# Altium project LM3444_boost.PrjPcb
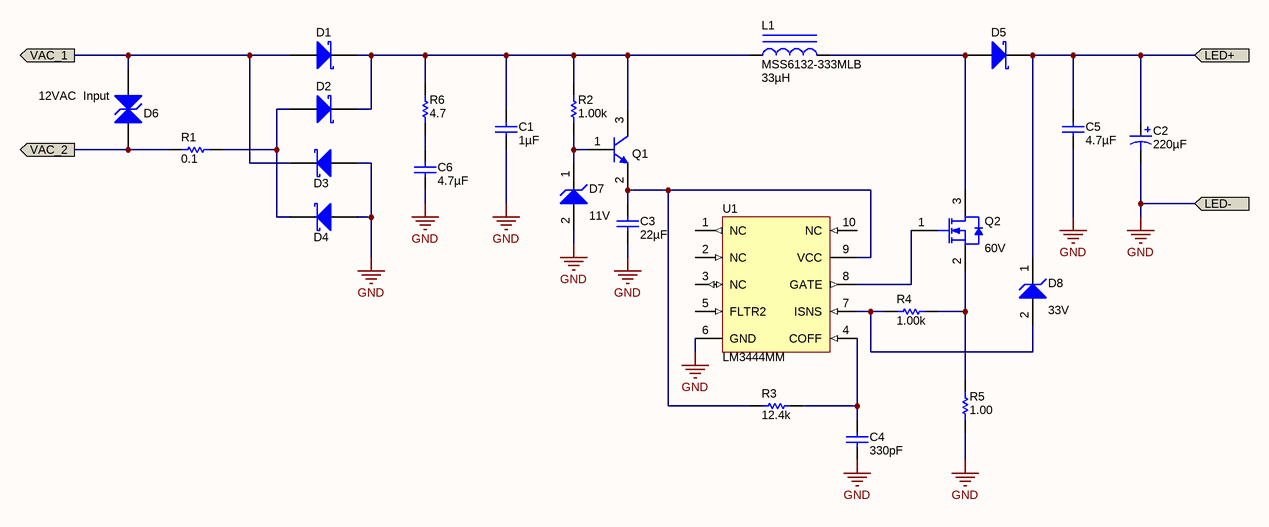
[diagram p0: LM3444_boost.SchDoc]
CopyrightYear: 2011; PCB_CopperRev: 001; PCB_SilkRev: REV A; PRJ_BasePN: xxxxxx; PRJ_Customer: Public Release; PRJ_Title: MR16 Boost Converter; SCH_Rev: 0; TechSupport: http://www.national.com/support
1 sheet, 24 parts. Net scope: flat (ports and power ports of the same name join across sheets).
Board file: MR16_boost.PcbDoc

## Sheet LM3444_boost.SchDoc
size B; Date: Not shown in title block; ApprovedBy: Not shown in title block; CheckedBy: Not shown in title block; Author: Not shown in title block; CompanyName: Not shown in title block; DrawnBy: Not shown in title block; Engineer: Not shown in title block; Organization: Not shown in title block; Address1: Not shown in title block; Address2: Not shown in title block; Address3: Not shown in title block; Address4: Not shown in title block; DocumentNumber: 1; Revision: Use project parameter SCH_Rev; SheetNumber: 1; SheetTotal: 1; PageSetup: Record=PageOptions|CenterHorizontal=True|CenterVertical=True|PrintScale=0.70|XCorrection=1.00|YCorrection=1.00|PrintKind=0|BorderSize=5000000|LeftOffset=0|BottomOffset=0|Orientation=2|PaperLength=1000|PaperWidth=1000|Scale=100|PaperSource=15|PrintQuality=600|MediaType=1|DitherType=10|PaperKind=Letter|PrintScaleMode=1

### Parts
C1  ValueDisplayed: 1µF  [0805_HV]  (hidden comment: GRM216R61E105KA12D)
C2  value 220µF  [Panasonic_ECA_8x11.5mm]  (hidden comment: ECA-1VHG221)
C3  ValueDisplayed: 22µF  [1210]  (hidden comment: GRM32ER61E226KE15L)
C4  ValueDisplayed: 330pF  [0603]  (hidden comment: 06031C331JAT2A)
C5  ValueDisplayed: 4.7µF  [1210]  (hidden comment: GRM32ER71H475KA88L)
C6  ValueDisplayed: 4.7µF  [0805_HV]  (hidden comment: GRM21BR61E475KA12L)
D1  B330A-13-F  [SMA]  (value not drawn)
D2  B330A-13-F  [SMA]  (value not drawn)
D3  B330A-13-F  [SMA]  (value not drawn)
D4  B330A-13-F  [SMA]  (value not drawn)
D5  B330A-13-F  [SMA]  (value not drawn)
D6  SMAJ24CA-13-F  [SMA]  (value not drawn)
D7  value 11V  [SOD-123]  (hidden comment: CMHZ4698)
D8  value 33V  [SOD-123]  (hidden comment: CMHZ4714)
L1  MSS6132-333MLB  ValueDisplayed: 33µH  [MSS6132]
Q1  BC848CLT1G  [SOT-23]  (value not drawn)
Q2  value 60V  [SOT-23]  (hidden comment: 2N7002ET1G)
R1  value 0.1  [0805_HV]  (hidden comment: ERJ-6RSJR10V)
R2  value 1.00k  [0603]  (hidden comment: CRCW06031K00FKEA)
R3  value 12.4k  [0603]  (hidden comment: CRCW060312K4FKEA)
R4  value 1.00k  [0603]  (hidden comment: CRCW06031K00FKEA)
R5  value 1.00  [1206]  (hidden comment: CSR 1/2 1 1 I)
R6  value 4.7  [0805_HV]  (hidden comment: RC0805JR-074R7L)
U1  LM3444MM  [MUB10A_N]

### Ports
LED+, LED-, VAC_1, VAC_2

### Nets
GND: C1.2 C2.2(-) C3.2 C4.2 C5.2 C6.2 D3.1(A) D4.1(A) D7.2(A) R5.1 U1.6(GND) ; port LED-
NetC1_1: C1.1 D1.2(K) D2.2(K) L1.1 Q1.3(C) R2.2 R6.2
NetC2_1: C2.1(+) C5.1 D5.2(K) D8.1(K) ; port LED+
NetC3_1: C3.1 Q1.2(E) R3.1 U1.9(VCC)
NetC4_1: C4.1 R3.2 U1.4(COFF)
NetC6_1: C6.1 R6.1
NetD1_1: D1.1(A) D3.2(K) D6.1(A) ; port VAC_1
NetD2_1: D2.1(A) D4.2(K) R1.2
NetD5_1: D5.1(A) L1.2 Q2.3(D)
NetD6_2: D6.2(K) R1.1 ; port VAC_2
NetD7_1: D7.1(K) Q1.1(B) R2.1
NetD8_2: D8.2(A) R4.2 U1.7(ISNS)
NetQ2_1: Q2.1(G) U1.8(GATE)
NetQ2_2: Q2.2(S) R4.1 R5.2

Not connected (* = marked no-connect by the designer): U1 1(NC) 2(NC) 3(NC) 5(FLTR2) 10(NC)

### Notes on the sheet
- (near D6) 12VAC  Input

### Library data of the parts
C1 = GRM216R61E105KA12D: CAP, CERM, 1uF, 25V, +/-10%, X5R, 0805; Manufacturer: MuRata; Cap_Case: 0805; ESR_Ohm: 0.009; Polarized: N; TaMax_C: 85; TaMin_C: -55; Tolerance_%: 10; VDC_V: 25; Cap_F: 0.000001; CompType: Capacitor; U/M: EA; Value1: 0.009 ohm
C2 = Capacitor_Polarized: CAP, AL, 220µF, 35V, +/-20%, TH bent; Manufacturer: Panasonic - ECG; Polarized: Y; Tolerance_%: 20; U/M: EA; Description: CAP ALUM 220UF 35V 20% RADIAL; Ripple Current: 270mA; Lifetime @ Temp.: 1000 Hrs @ 105°C
C3 = GRM32ER61E226KE15L: CAP, CERM, 22uF, 25V, +/-10%, X5R, 1210; Manufacturer: MuRata; ESR_Ohm: 0.002; Polarized: N; TaMax_C: 85; TaMin_C: -55; Tolerance_%: 10; VDC_V: 25; Cap_F: 0.000022; CompType: Capacitor; U/M: EA; Value1: 0.002 ohm
C4 = 06031C331JAT2A: CAP, CERM, 330pF, 100V, +/-5%, X7R, 0603; Manufacturer: AVX; ESR_Ohm: 0.472; Polarized: N; TaMax_C: 125; TaMin_C: -55; Tolerance_%: 5; VDC_V: 100; Cap_F: 0.00000000033; CompType: Capacitor; U/M: EA; Value1: 0.472 ohm
C5 = GRM32ER71H475KA88L: CAP, CERM, 4.7uF, 50V, +/-10%, X7R, 1210; Manufacturer: MuRata; ESR_Ohm: 0.002; Polarized: N; TaMax_C: 125; TaMin_C: -55; Tolerance_%: 10; VDC_V: 50; Cap_F: 0.0000047; CompType: Capacitor; U/M: EA; Value1: 0.002 ohm
C6 = GRM21BR61E475KA12L: CAP, CERM, 4.7uF, 25V, +/-10%, X5R, 0805; Manufacturer: MuRata; Cap_Case: 0805; ESR_Ohm: 0.004; Polarized: N; TaMax_C: 85; TaMin_C: -55; Tolerance_%: 10; VDC_V: 25; Cap_F: 0.0000047; CompType: Capacitor; U/M: EA; Value1: 0.004 ohm
D1-D5 = B330A-13-F: Diode, Schottky, 30V, 3A, SMA; Manufacturer: Diodes Inc.; RJC_CperW: 25; Vf_V: 0.5; Io_A: 3; Vr_V: 30; TJMax_C: 125; Value: 0.5V
D6 = TVS_Diode: TVS Diode, 400W, 24V, xx%, SMA; Manufacturer: Diodes Inc; CompType: Transorb; U/M: EA; Polarization: Bidirectional; Voltage - Breakdown: 26.7V; Description: TVS BI-DIR 24V 400W SMA
D7 = CMHZ4698: Diode, Zener, 11V, 500mW, SOD-123; Manufacturer: Central Semiconductor; U/M: EA; Power_W: 0.5; Vz: 11; Value1: 0.5W; RJA_CperW: 350
D8 = CMHZ4714: Diode, Zener, 33V, 500mW, SOD-123; Manufacturer: Central Semiconductor; U/M: EA; Power_W: 0.5; Vz: 33; Value1: 0.5W; RJA_CperW: 350
L1 = MSS6132-333MLB: Inductor, Shielded Drum Core, Ferrite, 33uH, 1.1A, 0.31 ohm, SMD; Manufacturer: Coilcraft; Ind_H: 33.0E-6; Imax_A: 1.1; Irms: 1.6A @ 40C rise; Isat: 1.1A @ 30% inductance drop; DCR_ohm: 0.31; U/M: EA
Q1 = BC848CLT1G, ON Semiconductor: Transistor, NPN, 30V, 0.1A, SOT-23; CompType: BJT; U/M: EA; PNP: 0; NPN: 1; Vceo_V: 30; Vcesat1_V: 0.7; Value: 0.7V; IcRated_A: 0.1; HfeMax: 800
Q2 = 2N7002ET1G: MOSFET, N-CH, 60V, 0.26A, SOT-23; Manufacturer: ON Semiconductor; U/M: EA; ChType: N; VdsMax_V: 60; Value1: 3 ohm; Rdson45_Ohm: 3; Value2: 0.81 nC; QgTyp_nC: 0.81; Vgs_V: 20; IdsMax_A: 0.26
R1 = ERJ-6RSJR10V: RES, 0.1 ohm, 5%, 0.125W, 0805; Manufacturer: Panasonic; CompType: Resistor; Tolerance_%: 5; Power_W: 0.125; Value_Code: R100; EIA_Code: E24; U/M: EA
R2 R4 = CRCW06031K00FKEA: RES, 1.00k ohm, 1%, 0.1W, 0603; Manufacturer: Vishay-Dale; CompType: Resistor; Tolerance_%: 1; VDC_V: 75; Power_W: 0.1; Res_ohm: 1000; Value_Code: 1k00; EIA_Code: E96; U/M: EA
R3 = CRCW060312K4FKEA: RES, 12.4k ohm, 1%, 0.1W, 0603; Manufacturer: Vishay-Dale; CompType: Resistor; Tolerance_%: 1; VDC_V: 75; Power_W: 0.1; Res_ohm: 12400; Value_Code: 12k4; EIA_Code: E96; U/M: EA
R5 = CSR 1/2 1 1 I: RES, 1.00 ohm, 1%, 0.5W, 1206; Manufacturer: Stackpole Electronics Inc; CompType: Resistor; Tolerance_%: 1; Power_W: 0.5; Value_Code: 1R00; EIA_Code: E96; U/M: EA
R6 = RC0805JR-074R7L: RES, 4.7 ohm, 5%, 0.125W, 0805; Manufacturer: Yageo America; CompType: Resistor; Tolerance_%: 5; VDC_V: 150; Power_W: 0.125; Value_Code: 4R70; EIA_Code: E24; U/M: EA
U1 = LM3445MM/NOPB: Triac Dimmable Offline LED Driver, 10-pin MSOP, Pb-Free; Manufacturer: National Semiconductor; PackageTopMarking: ZXTT*SULB; PowerWise: Y; CompType: MiscPower

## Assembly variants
-100A: all parts fitted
